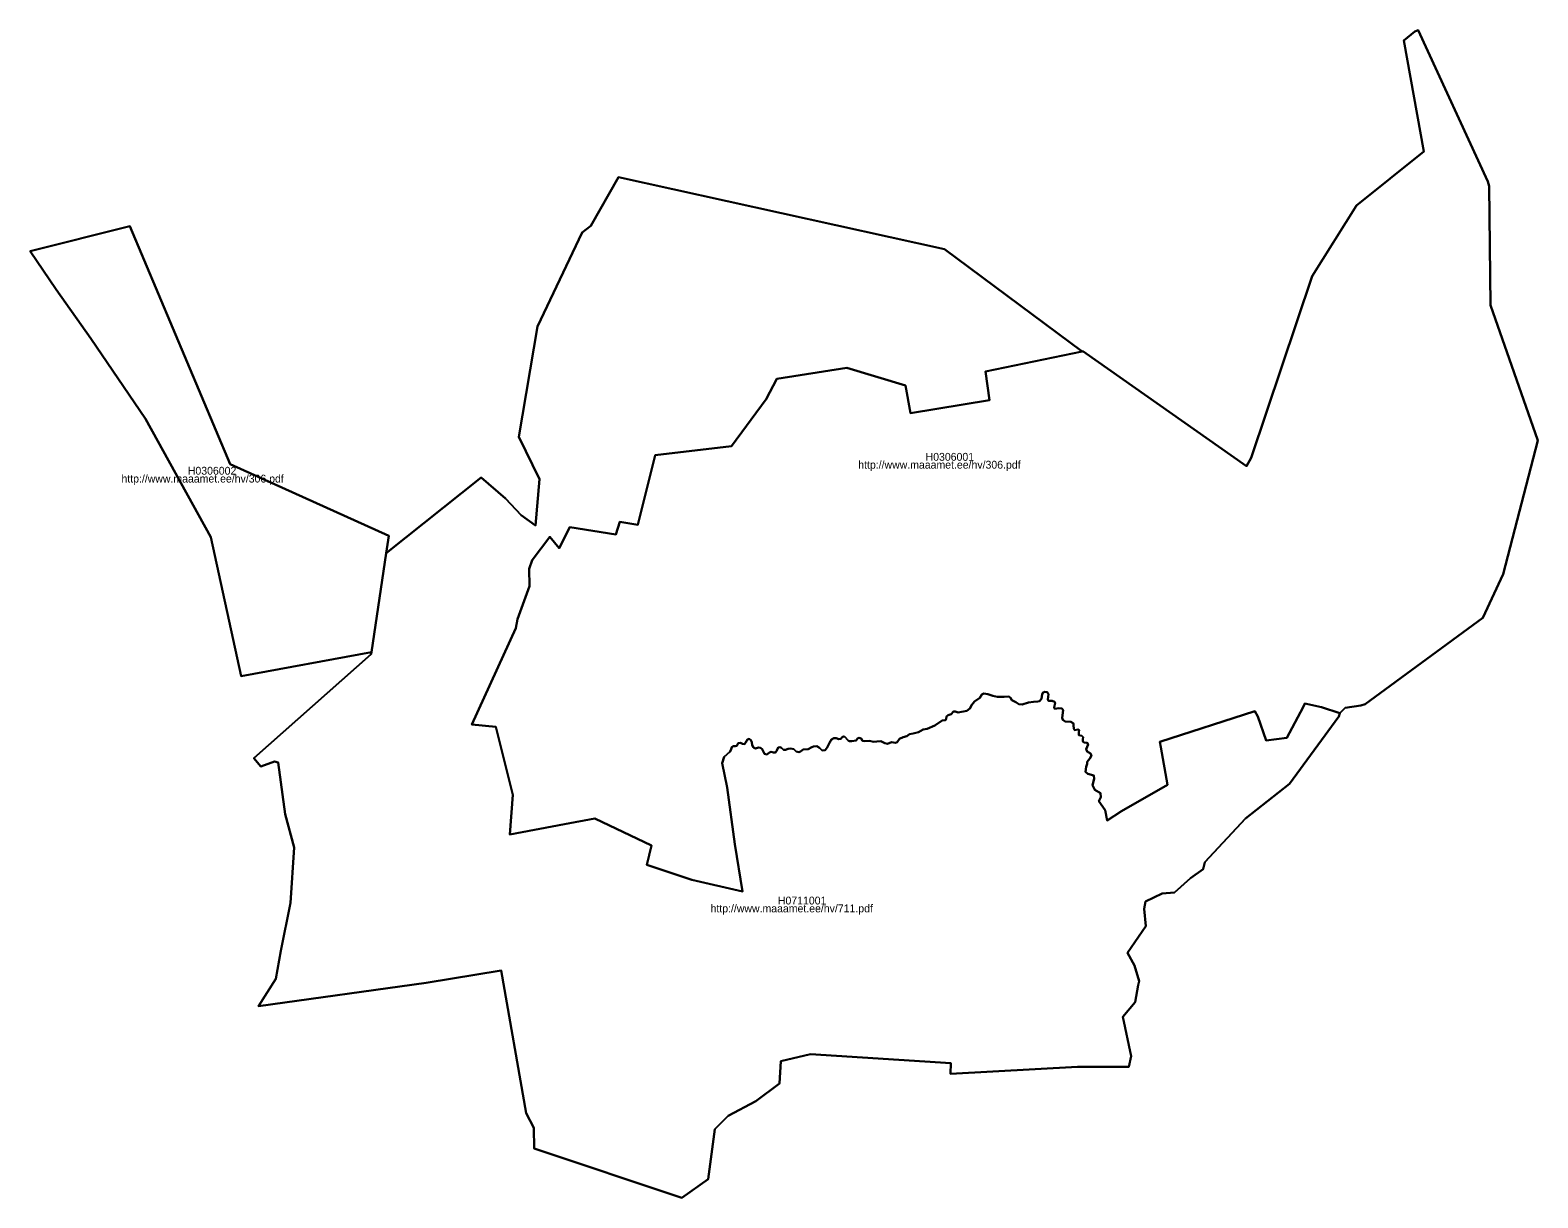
# Model space of a CAD drawing. Extents: x 369010 to 739155, y 6377141 to 6634081.
# Drawn here: x 553613 to 558411, y 6443873 to 6447588 of the extents above; entities that cross this region are included whole.
import ezdxf

# ---------------------------------------------------------------- set-up
doc = ezdxf.new("R2010")
doc.units = 0
for name, color, linetype in [('H_LINK', 7, 'Continuous'), ('H_PIIR', 7, 'Continuous'), ('H_TUNNUS', 7, 'Continuous')]:
    doc.layers.add(name, color=color, linetype=linetype)

msp = doc.modelspace()

# ---------------------------------------------------------------- linework, layer by layer
at = {"layer": 'H_PIIR'}
for points in [[(556960.8956, 6446565.8258), (556522.77, 6446891.17), (555485.9699, 6447120.14), (555397.1299, 6446965.93), (555369.66, 6446944), (555227.93, 6446645.28), (555168.7099, 6446294.2001), (555234.12, 6446159.2701), (555221.8601, 6446012.0701), (555175.5, 6446045.18), (555126.0499, 6446098.34), (555048.1801, 6446165.1), (554745.9223, 6445924.2518), (554754.16, 6445979.48), (554250.07, 6446207.34), (553930.7, 6446964.7101), (553613.04, 6446885.1201), (553696.1, 6446763.51), (553806.4199, 6446607.29), (553980.1599, 6446351.74), (554187.7799, 6445975.2101), (554284.64, 6445532.41), (554699.0099, 6445609.74), (554698.08, 6445602.4701), (554325.2101, 6445271.6899), (554347.42, 6445245.1699), (554390.4601, 6445261.72), (554402.4499, 6445258.13), (554424.26, 6445094.1201), (554453.13, 6444987.49), (554442.03, 6444812.0001), (554410.93, 6444658.72), (554395.38, 6444569.87), (554339.86, 6444483.23), (554873.2699, 6444556.74), (555112.35, 6444596.0799), (555191.3701, 6444142.97), (555215.81, 6444096.26), (555217.64, 6444030.46), (555687.58, 6443873.2201), (555770.96, 6443933.06), (555792.4599, 6444091.42), (555834.41, 6444134.4699), (555922.1699, 6444180.6699), (555997.69, 6444237.1), (556002.13, 6444308.1899), (556096.76, 6444330.03), (556543.1801, 6444301.49), (556542.5501, 6444268.06), (556946.2, 6444289.57), (557109.8201, 6444289.6999), (557117.2701, 6444323.97), (557090.45, 6444449.1301), (557129.76, 6444495.8001), (557139.7501, 6444550.13), (557143.1199, 6444562.3), (557127.6401, 6444612.3301), (557105.95, 6444652.35), (557164.0501, 6444737.28), (557158.0899, 6444792.4101), (557162.56, 6444816.25), (557216.2, 6444841.58), (557254.93, 6444844.56), (557305.58, 6444890.74), (557345.8101, 6444919.05), (557351.77, 6444941.4), (557480.49, 6445080.56), (557620.53, 6445190.82), (557778.4299, 6445404.89), (557781.67, 6445414.8399), (557797.74, 6445432.2301), (557848.54, 6445439.83), (557861.9999, 6445444.17), (558236.74, 6445718.56), (558300.6801, 6445857.5001), (558411.4401, 6446282.21), (558260.2901, 6446712.82), (558256.38, 6447092.1399), (558252.47, 6447106.26), (558030.0201, 6447588.08), (558020.0899, 6447583.96), (557985.0701, 6447555.14), (558048.32, 6447201.7799), (557833.7599, 6447030.78), (557693.47, 6446805.03), (557499.32, 6446227.7399), (557483.6701, 6446201.3401), (556963.7801, 6446566.4199)], [(556960.8956, 6446565.8258), (556963.7801, 6446566.4199), (557483.6701, 6446201.3401), (557499.32, 6446227.7399), (557693.47, 6446805.03), (557833.7599, 6447030.78), (558048.32, 6447201.7799), (557985.0701, 6447555.14), (558020.0899, 6447583.96), (558030.0201, 6447588.08), (558252.47, 6447106.26), (558256.38, 6447092.1399), (558260.2901, 6446712.82), (558411.4401, 6446282.21), (558300.6801, 6445857.5001), (558236.74, 6445718.56), (557861.9999, 6445444.17), (557848.54, 6445439.83), (557797.74, 6445432.2301), (557781.67, 6445414.8399), (557722.6, 6445433.75), (557669.61, 6445445.4801), (557664.8301, 6445434.18), (557612.71, 6445336.63), (557547.1301, 6445328.15), (557520.2, 6445404.63), (557511.09, 6445421.1499), (557208.3599, 6445323.58), (557211.61, 6445306.53), (557233.1199, 6445186.72), (557086.7101, 6445103.53), (557040.88, 6445073.3301), (557034.6799, 6445107), (557014.72, 6445135.6801), (557020.16, 6445147.39), (557019.7401, 6445160.3599), (557001.3501, 6445171.65), (556994.2399, 6445185.65), (556999.67, 6445206.77), (556997.99, 6445216.4901), (556978.88, 6445221.7001), (556971.7199, 6445228.0001), (556973.89, 6445244.0799), (556977.36, 6445253.64), (556976.71, 6445260.37), (556985.1801, 6445271.02), (556990.61, 6445280.14), (556987.79, 6445286.99), (556976.72, 6445292.85), (556974.33, 6445300.89), (556980.4099, 6445315.45), (556977.5901, 6445320.98), (556968.03, 6445322.0701), (556963.2501, 6445325.3299), (556962.82, 6445332.06), (556964.12, 6445339.2299), (556960.65, 6445342.7099), (556951.0901, 6445344.88), (556950.66, 6445354.66), (556951.5399, 6445361.2901), (556947.6301, 6445363.0201), (556938.2899, 6445360.85), (556934.3801, 6445365.1999), (556933.51, 6445376.7099), (556933.29, 6445382.5801), (556925.26, 6445387.57), (556907.2301, 6445388.8799), (556899.85, 6445393.98), (556897.68, 6445400.71), (556900.72, 6445424.39), (556896.6, 6445430.3699), (556887.26, 6445431.0199), (556874.67, 6445429.2899), (556872.0601, 6445432.7599), (556874.8799, 6445448.19), (556872.93, 6445451.45), (556865.98, 6445454.0499), (556854.25, 6445454.92), (556852.08, 6445459.05), (556853.82, 6445475.4499), (556849.91, 6445481.97), (556842.31, 6445483.27), (556837.09, 6445481.1), (556833.62, 6445475.67), (556832.0999, 6445460.89), (556825.7999, 6445453.5099), (556819.94, 6445451.7699), (556806.6899, 6445450.9), (556790.6199, 6445448.8299), (556770.4199, 6445442.75), (556759.36, 6445443.29), (556750.2299, 6445450.6801), (556737.86, 6445456.76), (556732.8599, 6445463.9301), (556727.8701, 6445468.4899), (556712.46, 6445466.8601), (556691.18, 6445467.51), (556676.4101, 6445469.9), (556660.56, 6445475.77), (556648.6199, 6445477.8301), (556641.45, 6445474.3501), (556635.3699, 6445464.36), (556618.6599, 6445452.53), (556609.75, 6445442.1001), (556603.46, 6445429.5), (556594.5501, 6445422.76), (556566.97, 6445417.1199), (556556.77, 6445420.92), (556551.7801, 6445420.27), (556543.7401, 6445411.58), (556534.19, 6445408.32), (556529.8399, 6445404.19), (556528.7601, 6445397.24), (556525.9301, 6445392.68), (556515.29, 6445391.37), (556492.2999, 6445376.1799), (556467.5401, 6445364.88), (556455.3699, 6445362.71), (556439.9501, 6445354.7799), (556423.6599, 6445350.44), (556411.72, 6445348.7), (556402.8099, 6445341.86), (556391.2999, 6445338.8201), (556380.01, 6445333.6001), (556372.4101, 6445322.74), (556366.98, 6445320.9001), (556353.9501, 6445322.6401), (556341.35, 6445317.4201), (556333.31, 6445319.5999), (556320.5001, 6445325.68), (556307.2501, 6445324.71), (556297.9201, 6445323.84), (556283.8, 6445326.88), (556267.72, 6445326.44), (556261.86, 6445327.43), (556257.73, 6445334.1701), (556251.87, 6445336.56), (556246.6601, 6445334.38), (556241.66, 6445327.8701), (556228.1901, 6445326.5599), (556220.16, 6445326.1301), (556216.25, 6445327.8701), (556206.04, 6445340.04), (556201.26, 6445340.4701), (556196.2699, 6445337.43), (556192.7899, 6445333.3), (556186.4899, 6445332.65), (556178.67, 6445336.13), (556170.8499, 6445335.9101), (556163.69, 6445331.56), (556157.82, 6445322.6501), (556149.79, 6445306.14), (556142.84, 6445297.7801), (556133.5001, 6445296.4799), (556125.03, 6445304.7401), (556116.34, 6445309.73), (556106.3501, 6445309.08), (556100.4899, 6445306.71), (556088.9699, 6445300.6199), (556073.77, 6445299.1), (556064.8701, 6445293.2301), (556059.22, 6445291.28), (556051.18, 6445293.56), (556043.58, 6445300.3), (556033.8, 6445302.69), (556025.77, 6445301.6), (556017.08, 6445298.13), (556011, 6445298.02), (556004.48, 6445305.1899), (555999.27, 6445307.15), (555993.62, 6445305.63), (555989.2801, 6445296.4999), (555984.93, 6445290.42), (555978.63, 6445289.98), (555971.47, 6445292.15), (555965.82, 6445290.53), (555957.9999, 6445284.0101), (555950.4, 6445285.5299), (555942.79, 6445300.5199), (555937.15, 6445304.87), (555931.0601, 6445305.8501), (555921.29, 6445302.81), (555915.4301, 6445305.63), (555910.87, 6445313.67), (555910, 6445322.5801), (555906.52, 6445329.32), (555900.8799, 6445333.5501), (555896.1, 6445331.8101), (555891.0999, 6445323.1199), (555886.32, 6445317.04), (555880.46, 6445317.9099), (555873.9401, 6445320.95), (555866.3401, 6445319.2101), (555864.39, 6445315.3), (555862.2099, 6445311.6101), (555858.3001, 6445310.08), (555850.49, 6445310.08), (555846.36, 6445306.5001), (555843.3101, 6445297.8101), (555839.4, 6445291.9399), (555822.03, 6445275.8601), (555815.3, 6445256.41), (555830.94, 6445178.4001), (555855.7, 6444998.2499), (555880.2701, 6444848.2099), (555718.44, 6444885.04), (555575.97, 6444932.4199), (555590.74, 6444994.3501), (555410.4799, 6445079.5299), (555313.17, 6445062.3601), (555139.8499, 6445028.9001), (555148.94, 6445155.2801), (555095.5701, 6445372.01), (555019.12, 6445379.0599), (555159.0401, 6445685.5601), (555164.26, 6445714.67), (555202.06, 6445819.4201), (555201.6199, 6445874.6099), (555210.7499, 6445902.22), (555266.7999, 6445975.88), (555296.8299, 6445939.76), (555330.2299, 6446006.73), (555477.5001, 6445983.91), (555490.0999, 6446023.46), (555547.01, 6446013.9001), (555601.76, 6446236.19), (555845.0401, 6446265.09), (555954.96, 6446413.7301), (555989.6999, 6446479.14), (556211.75, 6446514.0801), (556398.71, 6446457.9699), (556415.2, 6446369.34), (556666.76, 6446410.6699), (556653.65, 6446502.5301)], [(554745.9223, 6445924.2518), (555048.1801, 6446165.1), (555126.0499, 6446098.34), (555175.5, 6446045.18), (555221.8601, 6446012.0701), (555234.12, 6446159.2701), (555168.7099, 6446294.2001), (555227.93, 6446645.28), (555369.66, 6446944), (555397.1299, 6446965.93), (555485.9699, 6447120.14), (556522.77, 6446891.17), (556960.8956, 6446565.8258), (556653.65, 6446502.5301), (556666.76, 6446410.6699), (556415.2, 6446369.34), (556398.71, 6446457.9699), (556211.75, 6446514.0801), (555989.6999, 6446479.14), (555954.96, 6446413.7301), (555845.0401, 6446265.09), (555601.76, 6446236.19), (555547.01, 6446013.9001), (555490.0999, 6446023.46), (555477.5001, 6445983.91), (555330.2299, 6446006.73), (555296.8299, 6445939.76), (555266.7999, 6445975.88), (555210.7499, 6445902.22), (555201.6199, 6445874.6099), (555202.06, 6445819.4201), (555164.26, 6445714.67), (555159.0401, 6445685.5601), (555019.12, 6445379.0599), (555095.5701, 6445372.01), (555148.94, 6445155.2801), (555139.8499, 6445028.9001), (555313.17, 6445062.3601), (555410.4799, 6445079.5299), (555590.74, 6444994.3501), (555575.97, 6444932.4199), (555718.44, 6444885.04), (555880.2701, 6444848.2099), (555855.7, 6444998.2499), (555830.94, 6445178.4001), (555815.3, 6445256.41), (555822.03, 6445275.8601), (555839.4, 6445291.9399), (555843.3101, 6445297.8101), (555846.36, 6445306.5001), (555850.49, 6445310.08), (555858.3001, 6445310.08), (555862.2099, 6445311.6101), (555864.39, 6445315.3), (555866.3401, 6445319.2101), (555873.9401, 6445320.95), (555880.46, 6445317.9099), (555886.32, 6445317.04), (555891.0999, 6445323.1199), (555896.1, 6445331.8101), (555900.8799, 6445333.5501), (555906.52, 6445329.32), (555910, 6445322.5801), (555910.87, 6445313.67), (555915.4301, 6445305.63), (555921.29, 6445302.81), (555931.0601, 6445305.8501), (555937.15, 6445304.87), (555942.79, 6445300.5199), (555950.4, 6445285.5299), (555957.9999, 6445284.0101), (555965.82, 6445290.53), (555971.47, 6445292.15), (555978.63, 6445289.98), (555984.93, 6445290.42), (555989.2801, 6445296.4999), (555993.62, 6445305.63), (555999.27, 6445307.15), (556004.48, 6445305.1899), (556011, 6445298.02), (556017.08, 6445298.13), (556025.77, 6445301.6), (556033.8, 6445302.69), (556043.58, 6445300.3), (556051.18, 6445293.56), (556059.22, 6445291.28), (556064.8701, 6445293.2301), (556073.77, 6445299.1), (556088.9699, 6445300.6199), (556100.4899, 6445306.71), (556106.3501, 6445309.08), (556116.34, 6445309.73), (556125.03, 6445304.7401), (556133.5001, 6445296.4799), (556142.84, 6445297.7801), (556149.79, 6445306.14), (556157.82, 6445322.6501), (556163.69, 6445331.56), (556170.8499, 6445335.9101), (556178.67, 6445336.13), (556186.4899, 6445332.65), (556192.7899, 6445333.3), (556196.2699, 6445337.43), (556201.26, 6445340.4701), (556206.04, 6445340.04), (556216.25, 6445327.8701), (556220.16, 6445326.1301), (556228.1901, 6445326.5599), (556241.66, 6445327.8701), (556246.6601, 6445334.38), (556251.87, 6445336.56), (556257.73, 6445334.1701), (556261.86, 6445327.43), (556267.72, 6445326.44), (556283.8, 6445326.88), (556297.9201, 6445323.84), (556307.2501, 6445324.71), (556320.5001, 6445325.68), (556333.31, 6445319.5999), (556341.35, 6445317.4201), (556353.9501, 6445322.6401), (556366.98, 6445320.9001), (556372.4101, 6445322.74), (556380.01, 6445333.6001), (556391.2999, 6445338.8201), (556402.8099, 6445341.86), (556411.72, 6445348.7), (556423.6599, 6445350.44), (556439.9501, 6445354.7799), (556455.3699, 6445362.71), (556467.5401, 6445364.88), (556492.2999, 6445376.1799), (556515.29, 6445391.37), (556525.9301, 6445392.68), (556528.7601, 6445397.24), (556529.8399, 6445404.19), (556534.19, 6445408.32), (556543.7401, 6445411.58), (556551.7801, 6445420.27), (556556.77, 6445420.92), (556566.97, 6445417.1199), (556594.5501, 6445422.76), (556603.46, 6445429.5), (556609.75, 6445442.1001), (556618.6599, 6445452.53), (556635.3699, 6445464.36), (556641.45, 6445474.3501), (556648.6199, 6445477.8301), (556660.56, 6445475.77), (556676.4101, 6445469.9), (556691.18, 6445467.51), (556712.46, 6445466.8601), (556727.8701, 6445468.4899), (556732.8599, 6445463.9301), (556737.86, 6445456.76), (556750.2299, 6445450.6801), (556759.36, 6445443.29), (556770.4199, 6445442.75), (556790.6199, 6445448.8299), (556806.6899, 6445450.9), (556819.94, 6445451.7699), (556825.7999, 6445453.5099), (556832.0999, 6445460.89), (556833.62, 6445475.67), (556837.09, 6445481.1), (556842.31, 6445483.27), (556849.91, 6445481.97), (556853.82, 6445475.4499), (556852.08, 6445459.05), (556854.25, 6445454.92), (556865.98, 6445454.0499), (556872.93, 6445451.45), (556874.8799, 6445448.19), (556872.0601, 6445432.7599), (556874.67, 6445429.2899), (556887.26, 6445431.0199), (556896.6, 6445430.3699), (556900.72, 6445424.39), (556897.68, 6445400.71), (556899.85, 6445393.98), (556907.2301, 6445388.8799), (556925.26, 6445387.57), (556933.29, 6445382.5801), (556933.51, 6445376.7099), (556934.3801, 6445365.1999), (556938.2899, 6445360.85), (556947.6301, 6445363.0201), (556951.5399, 6445361.2901), (556950.66, 6445354.66), (556951.0901, 6445344.88), (556960.65, 6445342.7099), (556964.12, 6445339.2299), (556962.82, 6445332.06), (556963.2501, 6445325.3299), (556968.03, 6445322.0701), (556977.5901, 6445320.98), (556980.4099, 6445315.45), (556974.33, 6445300.89), (556976.72, 6445292.85), (556987.79, 6445286.99), (556990.61, 6445280.14), (556985.1801, 6445271.02), (556976.71, 6445260.37), (556977.36, 6445253.64), (556973.89, 6445244.0799), (556971.7199, 6445228.0001), (556978.88, 6445221.7001), (556997.99, 6445216.4901), (556999.67, 6445206.77), (556994.2399, 6445185.65), (557001.3501, 6445171.65), (557019.7401, 6445160.3599), (557020.16, 6445147.39), (557014.72, 6445135.6801), (557034.6799, 6445107), (557040.88, 6445073.3301), (557086.7101, 6445103.53), (557233.1199, 6445186.72), (557211.61, 6445306.53), (557208.3599, 6445323.58), (557511.09, 6445421.1499), (557520.2, 6445404.63), (557547.1301, 6445328.15), (557612.71, 6445336.63), (557664.8301, 6445434.18), (557669.61, 6445445.4801), (557722.6, 6445433.75), (557781.67, 6445414.8399), (557778.4299, 6445404.89), (557620.53, 6445190.82), (557480.49, 6445080.56), (557351.77, 6444941.4), (557345.8101, 6444919.05), (557305.58, 6444890.74), (557254.93, 6444844.56), (557216.2, 6444841.58), (557162.56, 6444816.25), (557158.0899, 6444792.4101), (557164.0501, 6444737.28), (557105.95, 6444652.35), (557127.6401, 6444612.3301), (557143.1199, 6444562.3), (557139.7501, 6444550.13), (557129.76, 6444495.8001), (557090.45, 6444449.1301), (557117.2701, 6444323.97), (557109.8201, 6444289.6999), (556946.2, 6444289.57), (556542.5501, 6444268.06), (556543.1801, 6444301.49), (556096.76, 6444330.03), (556002.13, 6444308.1899), (555997.69, 6444237.1), (555922.1699, 6444180.6699), (555834.41, 6444134.4699), (555792.4599, 6444091.42), (555770.96, 6443933.06), (555687.58, 6443873.2201), (555217.64, 6444030.46), (555215.81, 6444096.26), (555191.3701, 6444142.97), (555112.35, 6444596.0799), (554873.2699, 6444556.74), (554339.86, 6444483.23), (554395.38, 6444569.87), (554410.93, 6444658.72), (554442.03, 6444812.0001), (554453.13, 6444987.49), (554424.26, 6445094.1201), (554402.4499, 6445258.13), (554390.4601, 6445261.72), (554347.42, 6445245.1699), (554325.2101, 6445271.6899), (554698.08, 6445602.4701), (554699.0099, 6445609.74)], [(553930.7, 6446964.7101), (554250.07, 6446207.34), (554754.16, 6445979.48), (554745.9223, 6445924.2518), (554699.0099, 6445609.74), (554284.64, 6445532.41), (554187.7799, 6445975.2101), (553980.1599, 6446351.74), (553806.4199, 6446607.29), (553696.1, 6446763.51), (553613.04, 6446885.1201)]]:
    msp.add_lwpolyline(points, close=True, dxfattribs=at)

# ---------------------------------------------------------------- texts
at = {"layer": 'H_LINK'}
msp.add_text('http://www.maaamet.ee/hv/306.pdf', height=25, dxfattribs=at).set_placement((556248.553, 6446193.1449))
for s, p in [('http://www.maaamet.ee/hv/306.pdf', (553903.6256, 6446148.8804)), ('http://www.maaamet.ee/hv/711.pdf', (555778.4645, 6444781.4755))]:
    msp.add_text(s, height=25, rotation=360, dxfattribs=at).set_placement(p)
at = {"layer": 'H_TUNNUS'}
msp.add_text('H0306001', height=25, dxfattribs=at).set_placement((556462.9069, 6446218.1449))
for s, p in [('H0306002', (554114.8546, 6446173.8804)), ('H0711001', (555992.8184, 6444806.4755))]:
    msp.add_text(s, height=25, rotation=360, dxfattribs=at).set_placement(p)

doc.saveas('drawing.dxf')
